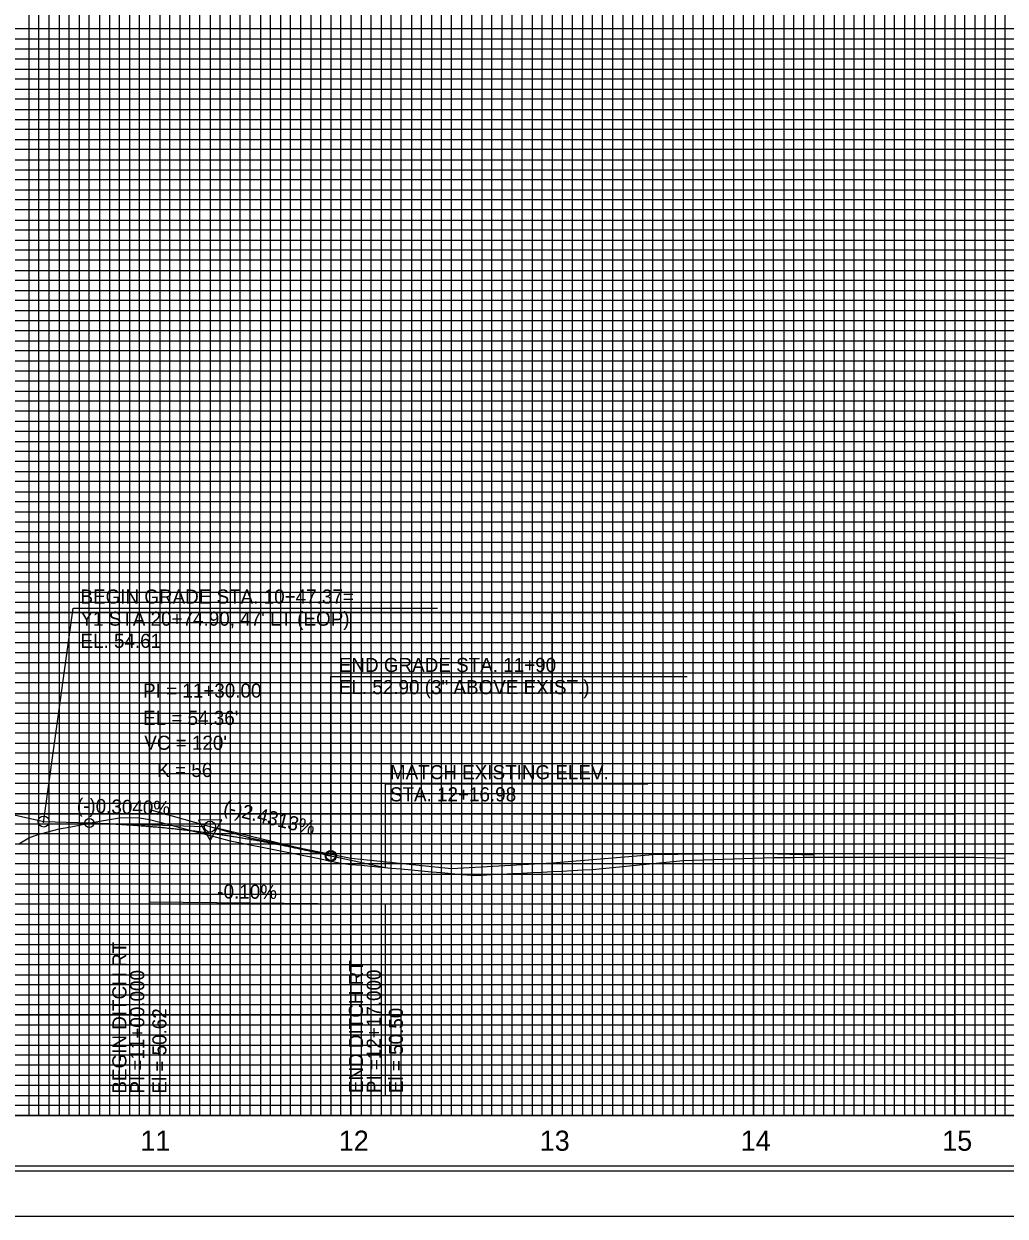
# Model space of a CAD drawing. Extents: x 2345490 to 2436403, y 465165 to 573888.
# Drawn here: x 2381804 to 2382292, y 532361 to 532954 of the extents above; entities that cross this region are included whole.
import ezdxf

# ---------------------------------------------------------------- set-up
doc = ezdxf.new("R2010")
doc.units = 0
for name, color, linetype in [('Old_Level_1', 7, 'Continuous'), ('Old_Level_18', 7, 'Continuous'), ('Old_Level_2', 7, 'Continuous'), ('Old_Level_3', 7, 'Continuous'), ('Old_Level_41', 7, 'Continuous'), ('Old_Level_42', 7, 'Continuous'), ('Old_Level_43', 7, 'Continuous'), ('Old_Level_50', 7, 'Continuous'), ('Old_Level_51', 7, 'Continuous'), ('Old_Level_57', 7, 'Continuous'), ('Old_Level_62', 7, 'Continuous'), ('Old_Level_63', 7, 'Continuous')]:
    doc.layers.add(name, color=color, linetype=linetype)

msp = doc.modelspace()

# ---------------------------------------------------------------- linework, layer by layer
at = {"layer": 'Old_Level_1'}
for points in [[(2381801.799, 532546.145), (2381806.799, 532549.13275), (2381811.799, 532550.8695), (2381816.799, 532552.128), (2381821.799, 532553.4715), (2381826.799, 532554.3915), (2381831.799, 532555.2835), (2381836.799, 532556.27575), (2381841.799, 532557.2585), (2381846.799, 532558.14025), (2381851.799, 532558.90725), (2381856.799, 532559.102), (2381861.799, 532559.02975), (2381866.799, 532558.10175), (2381871.799, 532556.787), (2381876.799, 532555.472), (2381881.799, 532554.15725), (2381886.799, 532552.84225), (2381891.799, 532551.5275), (2381896.799, 532550.2095), (2381901.799, 532548.89425), (2381906.799, 532547.6065), (2381911.799, 532546.603), (2381916.799, 532545.59575), (2381921.799, 532544.58425), (2381926.799, 532543.57275), (2381931.799, 532542.5615), (2381936.799, 532541.56275), (2381941.799, 532540.554), (2381946.799, 532539.54525), (2381951.799, 532538.5365), (2381956.799, 532537.528), (2381961.799, 532536.51925), (2381966.799, 532535.87925), (2381971.799, 532535.4215), (2381976.799, 532534.964), (2381981.799, 532534.5065), (2381986.799, 532534.04875), (2381991.799, 532533.59125), (2381996.799, 532533.121), (2382001.799, 532532.6625), (2382006.799, 532532.20425), (2382011.799, 532531.74575), (2382016.799, 532531.28725), (2382021.799, 532530.82875), (2382026.799, 532530.425), (2382031.799, 532530.49175), (2382036.799, 532530.76025), (2382041.799, 532531.0285), (2382046.799, 532531.29675), (2382051.799, 532531.56525), (2382056.799, 532531.8335), (2382061.799, 532532.00825), (2382066.799, 532532.2765), (2382071.799, 532532.54475), (2382076.799, 532532.81325), (2382081.799, 532533.0815), (2382086.799, 532533.35), (2382091.799, 532533.7715), (2382096.799, 532534.27475), (2382101.799, 532534.778), (2382106.799, 532535.28125), (2382111.799, 532535.78425), (2382116.799, 532536.2875), (2382121.799, 532536.79075), (2382126.799, 532537.294), (2382131.799, 532537.76775), (2382136.799, 532537.97175), (2382141.799, 532538.1305), (2382146.799, 532538.28925), (2382151.799, 532538.448), (2382156.799, 532538.61975), (2382161.799, 532538.778), (2382166.799, 532538.93525), (2382171.799, 532539.089), (2382176.799, 532539.2225), (2382181.799, 532539.289), (2382186.799, 532539.35175), (2382191.799, 532539.41125), (2382196.799, 532539.467), (2382201.799, 532539.50625), (2382206.799, 532539.50325), (2382211.799, 532539.495), (2382216.799, 532539.48275), (2382221.799, 532539.467), (2382226.799, 532539.44825), (2382231.799, 532539.45125), (2382236.799, 532539.46675), (2382241.799, 532539.47825), (2382246.799, 532539.48625), (2382251.799, 532539.4905), (2382256.799, 532539.415), (2382261.799, 532539.396), (2382266.799, 532539.393)], [(2382266.799, 532539.393), (2382271.799, 532539.3855), (2382276.799, 532539.37325), (2382281.799, 532539.31625), (2382286.799, 532539.1095), (2382291.799, 532538.9875)]]:
    msp.add_lwpolyline(points, dxfattribs=at)
at = {"layer": 'Old_Level_18'}
msp.add_lwpolyline([(2383216.79875, 533436.04975), (2381716.79875, 533436.04975), (2381716.79875, 532386.04975), (2383216.79875, 532386.04975)], close=True, dxfattribs=at)
at = {"layer": 'Old_Level_2'}
for p, q in [((2381791.799, 532562.18325), (2381814.16925, 532557.15)), ((2381814.16925, 532557.15), (2381836.799, 532556.46225)), ((2381836.799, 532556.46225), (2381894.0505, 532554.72175)), ((2381956.799, 532540.05), (2381899.47125, 532553.9885)), ((2381956.799, 532540.05), (2381983.779, 532534.35025))]:
    msp.add_line(p, q, dxfattribs=at)
msp.add_lwpolyline([(2381902.72475, 532557.9225), (2381890.98225, 532557.908), (2381896.86575, 532547.78975)], close=True, dxfattribs=at)
for centre, radius in [((2381814.16925, 532557.15), 2.75), ((2381836.799, 532556.46225), 2.25), ((2381896.799, 532554.638), 2.75), ((2381896.799, 532554.638), 2.75), ((2381956.799, 532540.05), 2.75), ((2381956.799, 532540.05), 2.25)]:
    msp.add_circle(centre, radius, dxfattribs=at)
msp.add_spline([(2381836.799, 532556.46225), (2381839.199, 532556.384), (2381841.599, 532556.29575), (2381843.999, 532556.19725), (2381846.399, 532556.0885), (2381848.799, 532555.96975), (2381851.199, 532555.8405), (2381853.599, 532555.70125), (2381855.999, 532555.55175), (2381858.399, 532555.392), (2381860.799, 532555.222), (2381863.199, 532555.04175), (2381865.599, 532554.8515), (2381867.999, 532554.65075), (2381870.399, 532554.44), (2381872.799, 532554.219), (2381875.199, 532553.98775), (2381877.599, 532553.74625), (2381879.999, 532553.49475), (2381882.399, 532553.23275), (2381884.799, 532552.96075), (2381887.199, 532552.6785), (2381889.599, 532552.386), (2381891.999, 532552.08325), (2381894.399, 532551.77025), (2381896.799, 532551.447), (2381899.199, 532551.11375), (2381901.599, 532550.77025), (2381903.999, 532550.4165), (2381906.399, 532550.0525), (2381908.799, 532549.67825), (2381911.199, 532549.29375), (2381913.599, 532548.89925), (2381915.999, 532548.4945), (2381918.399, 532548.0795), (2381920.799, 532547.65425), (2381923.199, 532547.21875), (2381925.599, 532546.773), (2381927.999, 532546.31725), (2381930.399, 532545.851), (2381932.799, 532545.37475), (2381935.199, 532544.88825), (2381937.599, 532544.3915), (2381939.999, 532543.8845), (2381942.399, 532543.3675), (2381944.799, 532542.84), (2381947.199, 532542.3025), (2381949.599, 532541.75475), (2381951.999, 532541.19675), (2381954.399, 532540.6285), (2381956.799, 532540.05)], degree=3, dxfattribs=at)
at = {"layer": 'Old_Level_3'}
for p, q in [((2381814.03875, 532556.54975), (2381828.82525, 532663.237)), ((2381828.82525, 532663.237), (2382009.71375, 532663.237)), ((2381956.799, 532540.05), (2381956.799, 532629.18325)), ((2381956.799, 532629.18325), (2382133.76675, 532629.18325)), ((2381983.77875, 532575.91425), (2381983.77875, 532534.35025)), ((2381983.77875, 532575.91425), (2382114.25025, 532575.91425)), ((2381866.799, 532517.25), (2381983.799, 532516.05)), ((2381866.799, 532517.25), (2381866.799, 532420.84507)), ((2381983.799, 532516.05), (2381983.799, 532420.84507))]:
    msp.add_line(p, q, dxfattribs=at)
at = {"layer": 'Old_Level_41'}
msp.add_line((2383216.79875, 532411.04975), (2381716.79875, 532411.04975), dxfattribs=at)
for points in [[(2381716.79875, 533436.04975), (2381766.79875, 533436.04975), (2381766.79875, 532411.04975), (2381816.79875, 532411.04975), (2381816.79875, 533436.04975), (2381866.79875, 533436.04975), (2381866.79875, 532411.04975), (2381916.79875, 532411.04975), (2381916.79875, 533436.04975), (2381966.79875, 533436.04975), (2381966.79875, 532411.04975), (2382016.79875, 532411.04975), (2382016.79875, 533436.04975), (2382066.79875, 533436.04975), (2382066.79875, 532411.04975), (2382116.79875, 532411.04975), (2382116.79875, 533436.04975), (2382166.79875, 533436.04975), (2382166.79875, 532411.04975), (2382216.79875, 532411.04975), (2382216.79875, 533436.04975), (2382266.79875, 533436.04975), (2382266.79875, 532411.04975), (2382316.79875, 532411.04975)], [(2381791.79875, 532411.04975), (2381791.79875, 533436.04975), (2381841.79875, 533436.04975), (2381841.79875, 532411.04975), (2381891.79875, 532411.04975), (2381891.79875, 533436.04975), (2381941.79875, 533436.04975), (2381941.79875, 532411.04975), (2381991.79875, 532411.04975), (2381991.79875, 533436.04975), (2382041.79875, 533436.04975), (2382041.79875, 532411.04975), (2382091.79875, 532411.04975), (2382091.79875, 533436.04975), (2382141.79875, 533436.04975), (2382141.79875, 532411.04975), (2382191.79875, 532411.04975), (2382191.79875, 533436.04975), (2382241.79875, 533436.04975), (2382241.79875, 532411.04975), (2382291.79875, 532411.04975), (2382291.79875, 533436.04975), (2382341.79875, 533436.04975)], [(2383216.79875, 532936.04975), (2381716.79875, 532936.04975), (2381716.79875, 532886.04975), (2383216.79875, 532886.04975)], [(2383216.79875, 532836.04975), (2381716.79875, 532836.04975), (2381716.79875, 532786.04975), (2383216.79875, 532786.04975)], [(2383216.79875, 532761.04975), (2381716.79875, 532761.04975), (2381716.79875, 532811.04975), (2383216.79875, 532811.04975)], [(2383216.79875, 532736.04975), (2381716.79875, 532736.04975), (2381716.79875, 532686.04975), (2383216.79875, 532686.04975)], [(2383216.79875, 532661.04975), (2381716.79875, 532661.04975), (2381716.79875, 532711.04975), (2383216.79875, 532711.04975)], [(2383216.79875, 532636.04975), (2381716.79875, 532636.04975), (2381716.79875, 532586.04975), (2383216.79875, 532586.04975)], [(2383216.79875, 532536.04975), (2381716.79875, 532536.04975), (2381716.79875, 532486.04975), (2383216.79875, 532486.04975)], [(2383216.79875, 532461.04975), (2381716.79875, 532461.04975), (2381716.79875, 532511.04975), (2383216.79875, 532511.04975)], [(2383216.79875, 532436.04975), (2381716.79875, 532436.04975)]]:
    msp.add_lwpolyline(points, dxfattribs=at)
at = {"layer": 'Old_Level_42'}
for points in [[(2383216.79875, 532861.04975), (2381716.79875, 532861.04975), (2381716.79875, 532911.04975), (2383216.79875, 532911.04975)], [(2383216.79875, 532561.04975), (2381716.79875, 532561.04975), (2381716.79875, 532611.04975), (2383216.79875, 532611.04975)]]:
    msp.add_lwpolyline(points, dxfattribs=at)
at = {"layer": 'Old_Level_43'}
for points in [[(2381806.79875, 533436.04975), (2381806.79875, 532411.04975), (2381811.79875, 532411.04975), (2381811.79875, 533436.04975)], [(2381821.79875, 533436.04975), (2381821.79875, 532411.04975), (2381826.79875, 532411.04975), (2381826.79875, 533436.04975)], [(2381831.79875, 533436.04975), (2381831.79875, 532411.04975), (2381836.79875, 532411.04975), (2381836.79875, 533436.04975)], [(2381846.79875, 533436.04975), (2381846.79875, 532411.04975), (2381851.79875, 532411.04975), (2381851.79875, 533436.04975)], [(2381856.79875, 533436.04975), (2381856.79875, 532411.04975), (2381861.79875, 532411.04975), (2381861.79875, 533436.04975)], [(2381871.79875, 533436.04975), (2381871.79875, 532411.04975), (2381876.79875, 532411.04975), (2381876.79875, 533436.04975)], [(2381881.79875, 533436.04975), (2381881.79875, 532411.04975), (2381886.79875, 532411.04975), (2381886.79875, 533436.04975)], [(2381896.79875, 533436.04975), (2381896.79875, 532411.04975), (2381901.79875, 532411.04975), (2381901.79875, 533436.04975)], [(2381906.79875, 533436.04975), (2381906.79875, 532411.04975), (2381911.79875, 532411.04975), (2381911.79875, 533436.04975)], [(2381921.79875, 533436.04975), (2381921.79875, 532411.04975), (2381926.79875, 532411.04975), (2381926.79875, 533436.04975)], [(2381931.79875, 532411.04975), (2381936.79875, 532411.04975), (2381936.79875, 533436.04975)], [(2381931.79875, 533436.04975), (2381931.79875, 532411.04975)], [(2381946.79875, 533436.04975), (2381946.79875, 532411.04975), (2381951.79875, 532411.04975), (2381951.79875, 533436.04975)], [(2381956.79875, 533436.04975), (2381956.79875, 532411.04975), (2381961.79875, 532411.04975), (2381961.79875, 533436.04975)], [(2381971.79875, 533436.04975), (2381971.79875, 532411.04975), (2381976.79875, 532411.04975), (2381976.79875, 533436.04975)], [(2381981.79875, 533436.04975), (2381981.79875, 532411.04975), (2381986.79875, 532411.04975), (2381986.79875, 533436.04975)], [(2381996.79875, 533436.04975), (2381996.79875, 532411.04975), (2382001.79875, 532411.04975), (2382001.79875, 533436.04975)], [(2382006.79875, 533436.04975), (2382006.79875, 532411.04975), (2382011.79875, 532411.04975), (2382011.79875, 533436.04975)], [(2382021.79875, 533436.04975), (2382021.79875, 532411.04975), (2382026.79875, 532411.04975), (2382026.79875, 533436.04975)], [(2382031.79875, 533436.04975), (2382031.79875, 532411.04975), (2382036.79875, 532411.04975), (2382036.79875, 533436.04975)], [(2382046.79875, 533436.04975), (2382046.79875, 532411.04975), (2382051.79875, 532411.04975), (2382051.79875, 533436.04975)], [(2382056.79875, 533436.04975), (2382056.79875, 532411.04975), (2382061.79875, 532411.04975), (2382061.79875, 533436.04975)], [(2382071.79875, 533436.04975), (2382071.79875, 532411.04975), (2382076.79875, 532411.04975), (2382076.79875, 533436.04975)], [(2382081.79875, 533436.04975), (2382081.79875, 532411.04975), (2382086.79875, 532411.04975), (2382086.79875, 533436.04975)], [(2382096.79875, 533436.04975), (2382096.79875, 532411.04975), (2382111.79875, 532411.04975), (2382111.79875, 533436.04975)], [(2382101.79875, 533436.04975), (2382101.79875, 532411.04975), (2382106.79875, 532411.04975), (2382106.79875, 533436.04975)], [(2382101.79875, 533435.44975), (2382101.79875, 532411.04975), (2382106.79875, 532411.04975), (2382106.79875, 533435.44975)], [(2382121.79875, 533436.04975), (2382121.79875, 532411.04975), (2382126.79875, 532411.04975), (2382126.79875, 533436.04975)], [(2382131.79875, 533436.04975), (2382131.79875, 532411.04975), (2382136.79875, 532411.04975), (2382136.79875, 533436.04975)], [(2382146.79875, 533436.04975), (2382146.79875, 532411.04975), (2382151.79875, 532411.04975), (2382151.79875, 533436.04975)], [(2382156.79875, 533436.04975), (2382156.79875, 532411.04975), (2382161.79875, 532411.04975), (2382161.79875, 533436.04975)], [(2382171.79875, 533436.04975), (2382171.79875, 532411.04975), (2382176.79875, 532411.04975), (2382176.79875, 533436.04975)], [(2382181.79875, 533436.04975), (2382181.79875, 532411.04975), (2382186.79875, 532411.04975), (2382186.79875, 533436.04975)], [(2382196.79875, 533436.04975), (2382196.79875, 532411.04975), (2382201.79875, 532411.04975), (2382201.79875, 533436.04975)], [(2382206.79875, 533436.04975), (2382206.79875, 532411.04975), (2382211.79875, 532411.04975), (2382211.79875, 533436.04975)], [(2382221.79875, 533436.04975), (2382221.79875, 532411.04975), (2382226.79875, 532411.04975), (2382226.79875, 533436.04975)], [(2382231.79875, 533436.04975), (2382231.79875, 532411.04975), (2382236.79875, 532411.04975), (2382236.79875, 533436.04975)], [(2382246.79875, 533436.04975), (2382246.79875, 532411.04975)], [(2382251.79875, 533436.04975), (2382251.79875, 532411.04975), (2382256.79875, 532411.04975), (2382256.79875, 533436.04975), (2382261.79875, 533436.04975), (2382261.79875, 532411.04975), (2382271.79875, 532411.04975), (2382271.79875, 533436.04975), (2382276.79875, 533436.04975), (2382276.79875, 532411.04975), (2382281.79875, 532411.04975), (2382281.79875, 533436.04975), (2382286.79875, 533436.04975), (2382286.79875, 532411.04975)], [(2383166.79875, 532951.04975), (2381766.79875, 532951.04975), (2381766.79875, 532946.04975), (2383166.79875, 532946.04975)], [(2383166.79875, 532941.04975), (2381766.79875, 532941.04975), (2381766.79875, 532931.04975), (2383166.79875, 532931.04975)], [(2383166.79875, 532926.04975), (2381766.79875, 532926.04975), (2381766.79875, 532921.04975), (2383166.79875, 532921.04975)], [(2383166.79875, 532916.04975), (2381766.79875, 532916.04975)], [(2381766.79875, 532906.04975), (2383166.79875, 532906.04975)], [(2383166.79875, 532901.04975), (2381766.79875, 532901.04975), (2381766.79875, 532896.04975), (2383166.79875, 532896.04975)], [(2383166.79875, 532891.04975), (2381766.79875, 532891.04975), (2381766.79875, 532881.04975), (2383166.79875, 532881.04975)], [(2383166.79875, 532876.04975), (2381766.79875, 532876.04975), (2381766.79875, 532871.04975), (2383166.79875, 532871.04975)], [(2383166.79875, 532866.04975), (2381766.79875, 532866.04975), (2381766.79875, 532856.04975), (2383166.79875, 532856.04975)], [(2383166.79875, 532851.04975), (2381766.79875, 532851.04975), (2381766.79875, 532846.04975), (2383166.79875, 532846.04975)], [(2383166.79875, 532841.04975), (2381766.79875, 532841.04975), (2381766.79875, 532831.04975), (2383166.79875, 532831.04975)], [(2383166.79875, 532826.04975), (2381766.79875, 532826.04975), (2381766.79875, 532821.04975), (2383166.79875, 532821.04975)], [(2383166.79875, 532816.04975), (2381766.79875, 532816.04975), (2381766.79875, 532806.04975), (2383166.79875, 532806.04975)], [(2383166.79875, 532801.04975), (2381766.79875, 532801.04975), (2381766.79875, 532796.04975), (2383166.79875, 532796.04975)], [(2383166.79875, 532791.04975), (2381766.79875, 532791.04975), (2381766.79875, 532781.04975), (2383166.79875, 532781.04975)], [(2383166.79875, 532776.04975), (2381766.79875, 532776.04975), (2381766.79875, 532771.04975), (2383166.79875, 532771.04975)], [(2383166.79875, 532766.04975), (2381766.79875, 532766.04975), (2381766.79875, 532756.04975), (2383166.79875, 532756.04975)], [(2383166.79875, 532751.04975), (2381766.79875, 532751.04975), (2381766.79875, 532746.04975), (2383166.79875, 532746.04975)], [(2383166.79875, 532741.04975), (2381766.79875, 532741.04975), (2381766.79875, 532731.04975), (2383166.79875, 532731.04975)], [(2383166.79875, 532726.04975), (2381766.79875, 532726.04975), (2381766.79875, 532721.04975), (2383166.79875, 532721.04975)], [(2383166.79875, 532716.04975), (2381766.79875, 532716.04975), (2381766.79875, 532706.04975), (2383166.79875, 532706.04975)], [(2383166.79875, 532701.04975), (2381766.79875, 532701.04975), (2381766.79875, 532696.04975), (2383166.79875, 532696.04975)], [(2383166.79875, 532691.04975), (2381766.79875, 532691.04975), (2381766.79875, 532681.04975), (2383166.79875, 532681.04975)], [(2383166.79875, 532676.04975), (2381766.79875, 532676.04975), (2381766.79875, 532671.04975), (2383166.79875, 532671.04975)], [(2383166.79875, 532666.04975), (2381766.79875, 532666.04975), (2381766.79875, 532656.04975), (2383166.79875, 532656.04975)], [(2383166.79875, 532651.04975), (2381766.79875, 532651.04975), (2381766.79875, 532646.04975), (2383166.79875, 532646.04975)], [(2383166.79875, 532641.04975), (2381766.79875, 532641.04975), (2381766.79875, 532631.04975), (2383166.79875, 532631.04975)], [(2383166.79875, 532626.04975), (2381766.79875, 532626.04975), (2381766.79875, 532621.04975), (2383166.79875, 532621.04975)], [(2383166.79875, 532616.04975), (2381766.79875, 532616.04975)], [(2381766.79875, 532606.04975), (2383166.79875, 532606.04975)], [(2383166.79875, 532601.04975), (2381766.79875, 532601.04975), (2381766.79875, 532596.04975), (2383166.79875, 532596.04975)], [(2383166.79875, 532591.04975), (2381766.79875, 532591.04975)], [(2381766.79875, 532581.04975), (2383166.79875, 532581.04975)], [(2383166.79875, 532576.04975), (2381766.79875, 532576.04975), (2381766.79875, 532571.04975), (2383166.79875, 532571.04975)], [(2383166.79875, 532566.04975), (2381766.79875, 532566.04975), (2381766.79875, 532556.04975), (2383166.79875, 532556.04975)], [(2383166.79875, 532551.04975), (2381766.79875, 532551.04975), (2381766.79875, 532546.04975), (2383166.79875, 532546.04975)], [(2383166.79875, 532541.04975), (2381766.79875, 532541.04975), (2381766.79875, 532531.04975), (2383166.79875, 532531.04975)], [(2383166.79875, 532526.04975), (2381766.79875, 532526.04975), (2381766.79875, 532521.04975), (2383166.79875, 532521.04975)], [(2383166.79875, 532516.04975), (2381766.79875, 532516.04975), (2381766.79875, 532506.04975), (2383166.79875, 532506.04975)], [(2383166.79875, 532501.04975), (2381766.79875, 532501.04975), (2381766.79875, 532496.04975), (2383166.79875, 532496.04975)], [(2383166.79875, 532491.04975), (2381766.79875, 532491.04975), (2381766.79875, 532481.04975), (2383166.79875, 532481.04975)], [(2383166.79875, 532476.04975), (2381766.79875, 532476.04975), (2381766.79875, 532471.04975), (2383166.79875, 532471.04975)], [(2383166.79875, 532466.04975), (2381766.79875, 532466.04975), (2381766.79875, 532456.04975), (2383166.79875, 532456.04975)], [(2383166.79875, 532451.04975), (2381766.79875, 532451.04975), (2381766.79875, 532446.04975), (2383166.79875, 532446.04975)], [(2383166.79875, 532441.04975), (2381766.79875, 532441.04975), (2381766.79875, 532431.04975), (2383166.79875, 532431.04975)], [(2383166.79875, 532426.04975), (2381766.79875, 532426.04975), (2381766.79875, 532421.04975), (2383166.79875, 532421.04975)], [(2383166.79875, 532416.04975), (2381766.79875, 532416.04975)]]:
    msp.add_lwpolyline(points, dxfattribs=at)
at = {"layer": 'Old_Level_50'}
msp.add_lwpolyline([(2383229.29875, 533438.59975), (2381562.79875, 533438.59975), (2381562.79875, 532383.49975), (2383229.29875, 532383.49975)], close=True, dxfattribs=at)
at = {"layer": 'Old_Level_51'}
msp.add_lwpolyline([(2383233.79875, 533461.04975), (2381549.79875, 533461.04975), (2381549.79875, 532361.04975), (2383233.79875, 532361.04975)], close=True, dxfattribs=at)
at = {"layer": 'Old_Level_57'}
for p, q in [((2381716.79925, 532661.05025), (2382266.79875, 532661.05025)), ((2381866.79875, 532411.05025), (2381866.79875, 532661.05025)), ((2381966.79875, 532411.05025), (2381966.79875, 532661.05025)), ((2382066.79875, 532411.05025), (2382066.79875, 532661.05025)), ((2382166.79875, 532411.05025), (2382166.79875, 532661.05025)), ((2382266.79875, 532411.05025), (2382266.79875, 532661.05025)), ((2381716.79925, 532611.05025), (2382266.79875, 532611.05025)), ((2381716.79925, 532561.05025), (2382266.79875, 532561.05025)), ((2381716.79925, 532511.05025), (2382266.79875, 532511.05025)), ((2381716.799, 532461.05025), (2382266.79875, 532461.05025)), ((2381716.79925, 532411.05025), (2382266.79875, 532411.05025))]:
    msp.add_line(p, q, dxfattribs=at)
at = {"layer": 'Old_Level_63'}
msp.add_line((2381766.79875, 532411.04975), (2382198.83425, 532411.04975), dxfattribs=at)
msp.add_lwpolyline([(2381866.799, 532563.05), (2381916.799, 532549.05), (2381966.799, 532538.95), (2382016.799, 532533.85), (2382066.799, 532536.65), (2382116.799, 532540.85), (2382166.799, 532541.35), (2382196.799, 532540.55)], dxfattribs=at)

# ---------------------------------------------------------------- texts
at = {"layer": 'Old_Level_2'}
for s, height, p in [('BEGIN GRADE STA. 10+47.37=', 7.0000005, (2381832.41675, 532665.46)), ("Y1 STA 20+74.90, 47' LT (EOP)", 7.0000005, (2381832.41675, 532654.46)), ('EL. 54.61', 7.000001, (2381832.41675, 532643.46)), ('END GRADE STA. 11+90', 7.0000005, (2381960.788, 532631.4475)), ('PI = 11+30.00', 7.0000005, (2381863.519, 532618.7195)), ('EL. 52.90 (3" ABOVE EXIST.)', 7.0000005, (2381960.788, 532620.4475)), ("EL = 54.36'", 7.0000005, (2381863.5195, 532605.171)), ("VC = 120'", 7.000001, (2381864.124, 532592.79775)), ('K = 56', 7.000001, (2381870.573, 532579.2735)), ('MATCH EXISTING ELEV.', 7.0000005, (2381986.16675, 532578.17825)), ('STA. 12+16.98', 7.0000005, (2381986.16675, 532567.17825))]:
    msp.add_text(s, height=height, dxfattribs=at).set_placement(p)
for s, rotation, p in [('(-)0.3040%', 358.25869167, (2381830.54325, 532561.69675)), ('(-)2.4313%', 346.33466389, (2381902.9915, 532561.28375))]:
    msp.add_text(s, height=7.000001, rotation=rotation, dxfattribs=at).set_placement(p)
at = {"layer": 'Old_Level_3'}
for s, height, rotation, p in [('-0.10%', 7, 359.4124, (2381900.3665, 532518.971)), ('BEGIN DITCH RT', 7.0000005, 90, (2381855.24905, 532421.93915)), ('END DITCH RT', 7.0000005, 90, (2381972.75967, 532422.18661)), ('PI =11+00.000', 7.0000005, 90, (2381864.12295, 532421.93915)), ('PI =12+17.000', 7.0000005, 90, (2381981.63358, 532422.18661)), ('El = 50.62', 7.000001, 90, (2381875.12295, 532421.93915)), ('El = 50.50', 7.000001, 90, (2381992.63358, 532422.18661))]:
    msp.add_text(s, height=height, rotation=rotation, dxfattribs=at).set_placement(p)
at = {"layer": 'Old_Level_62'}
for s, p in [('11', (2381862.222, 532393.55)), ('12', (2381960.77025, 532393.55)), ('13', (2382060.605, 532393.55)), ('14', (2382160.4475, 532393.55)), ('15', (2382260.54, 532393.55))]:
    msp.add_text(s, height=10.000001, dxfattribs=at).set_placement(p)

doc.saveas('drawing.dxf')
